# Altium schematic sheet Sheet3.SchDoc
size A4
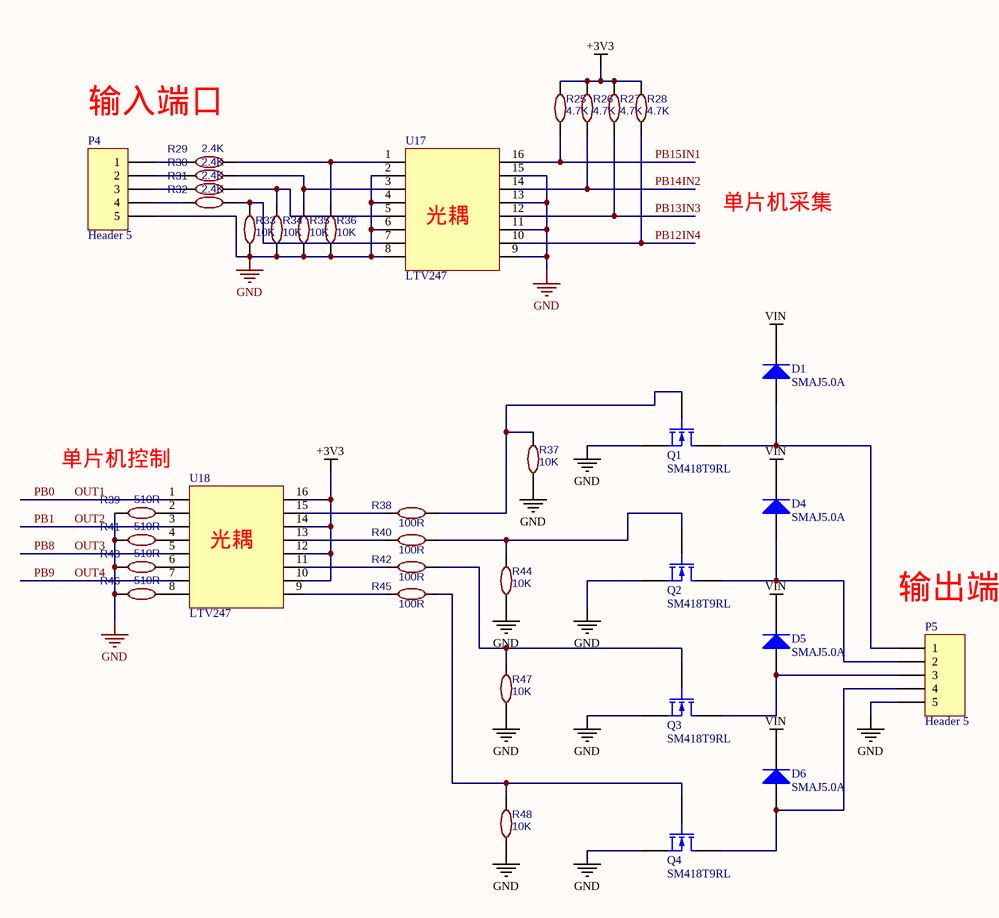
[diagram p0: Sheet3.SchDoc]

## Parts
D1  SMAJ5.0A  [DO214-SMA-SOAC]
D4  SMAJ5.0A  [DO214-SMA-SOAC]
D5  SMAJ5.0A  [DO214-SMA-SOAC]
D6  SMAJ5.0A  [DO214-SMA-SOAC]
P4  Header 5  [HDR1X5]
P5  Header 5  [HDR1X5]
Q1  SM418T9RL  [TO252-3]
Q2  SM418T9RL  [TO252-3]
Q3  SM418T9RL  [TO252-3]
Q4  SM418T9RL  [TO252-3]
R25  4.7K  [R0603]
R26  4.7K  [R0603]
R27  4.7K  [R0603]
R28  4.7K  [R0603]
R29  2.4K  [R0603]
R30  2.4K  [R0603]
R31  2.4K  [R0603]
R32  2.4K  [R0603]
R33  10K  [R0603]
R34  10K  [R0603]
R35  10K  [R0603]
R36  10K  [R0603]
R37  10K  [R0603]
R38  100R  [R0603]
R39  510R  [R0603]
R40  100R  [R0603]
R41  510R  [R0603]
R42  100R  [R0603]
R43  510R  [R0603]
R44  10K  [R0603]
R45  100R  [R0603]
R46  510R  [R0603]
R47  10K  [R0603]
R48  10K  [R0603]
U17  LTV247  [SOIC-16-M]
U18  LTV247  [SOIC-16-M]

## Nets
+3V3: R25.2 R26.2 R27.2 R28.2 U18.10 U18.12 U18.14 U18.16
GND: P4.5 P5.5 Q1.3(S) Q2.3(S) Q3.3(S) Q4.3(S) R33.1 R34.1 R35.1 R36.1 R37.2 R39.1 R41.1 R43.1 R44.2 R46.1 R47.2 R48.2 U17.2 U17.4 U17.6 U17.8 U17.9 U17.11 U17.13 U17.15
VIN: D1.2(K) D4.2(K) D5.2(K) D6.2(K)
IN1: R25.1 U17.16  [also labelled PB15]
IN2: R26.1 U17.14  [also labelled PB14]
IN3: R27.1 U17.12  [also labelled PB13]
IN4: R28.1 U17.10  [also labelled PB12]
OUT1: U18.1  [also labelled PB0]
OUT2: U18.3  [also labelled PB1]
OUT3: U18.5  [also labelled PB8]
OUT4: U18.7  [also labelled PB9]
NetD1_1: D1.1(A) P5.1 Q1.1(D)
NetD4_1: D4.1(A) P5.2 Q2.1(D)
NetD5_1: D5.1(A) P5.3 Q3.1(D)
NetD6_1: D6.1(A) P5.4 Q4.1(D)
NetP4_1: P4.1 R29.1
NetP4_2: P4.2 R30.1
NetP4_3: P4.3 R31.1
NetP4_4: P4.4 R32.1
NetQ1_2: Q1.2(G) R37.1 R38.2
NetQ2_2: Q2.2(G) R40.2 R44.1
NetQ3_2: Q3.2(G) R42.2 R47.1
NetQ4_2: Q4.2(G) R45.2 R48.1
NetR29_2: R29.2 R36.2 U17.1
NetR30_2: R30.2 R35.2 U17.3
NetR31_2: R31.2 R34.2 U17.5
NetR32_2: R32.2 R33.2 U17.7
NetR38_1: R38.1 U18.15
NetR39_2: R39.2 U18.2
NetR40_1: R40.1 U18.13
NetR41_2: R41.2 U18.4
NetR42_1: R42.1 U18.11
NetR43_2: R43.2 U18.6
NetR45_1: R45.1 U18.9
NetR46_2: R46.2 U18.8

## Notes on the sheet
- 输入端口
- (near U17) 光耦
- 单片机采集
- (near R39) 单片机控制
- (near U18) 光耦
- (near P5) 输出端口

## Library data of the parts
D1 D4-D6 = Diode: Default Diode
P4 P5 = Header 5: Header, 5-Pin 隔离输入输出5P
Q1-Q4 = MOSFET-N: N-Channel MOSFET
R25-R48 = 1K: BOM_Manufacturer: UniOhm; BOM_Manufacturer Part: 0603WAF1001T5E; nameAlias: Resistance (Ohms); SMT Type: Basic
U17 U18 = SOP-16: 光耦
